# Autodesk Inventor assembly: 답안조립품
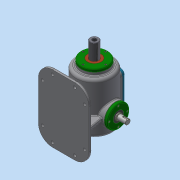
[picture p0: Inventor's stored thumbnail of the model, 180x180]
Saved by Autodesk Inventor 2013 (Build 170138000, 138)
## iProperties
Created: 2019-10
Part Number: 답안조립품
Document SubType Name: Assembly
Designer: dgall
Author: dgall
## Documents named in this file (17)
- C:\Users\dgall\Desktop\391004V1035\답안조립품.iam
- C:\Users\dgall\Desktop\391004V1035\본체.ipt
- C:\Users\dgall\Desktop\391004V1035\개스킷 B.ipt
- C:\Users\dgall\Desktop\391004V1035\베어링 6205.ipt
- 베어링 6205.ipt
- C:\Users\dgall\Desktop\391004V1035\볼트 M4x0.7.ipt
- C:\Users\dgall\Desktop\391004V1035\오일 실 25 38 8.ipt
- C:\Users\dgall\Desktop\391004V1035\축 커버.ipt
- C:\Users\dgall\Desktop\391004V1035\고정플레이트.ipt
- C:\Users\dgall\Desktop\391004V1035\상부커버.ipt
- C:\Users\dgall\Desktop\391004V1035\육각머리볼트 M4.ipt
- C:\Users\dgall\Desktop\391004V1035\가변스프링.ipt
- C:\Users\dgall\Desktop\391004V1035\개스킷 A.ipt
- C:\Users\dgall\Desktop\391004V1035\부시.ipt
- C:\Users\dgall\Desktop\391004V1035\슬라이드 커버.ipt
- C:\Users\dgall\Desktop\391004V1035\슬라이드.ipt
- C:\Users\dgall\Desktop\391004V1035\편심축.ipt
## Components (17 placed, 5 different names)
1. 개스킷 B:1
2. M4x0.7:1
3. M4x0.7:2
4. M4x0.7:3
5. M4x0.7:4
6. 개스킷 B:2
7. M4x0.7:5
8. M4x0.7:6
9. M4x0.7:7
10. M4x0.7:8
11. 고정플레이트:1 — 플러쉬:1
12. 가변스프링:1
13. 개스킷 A:1
14. M4x0.7:9
15. M4x0.7:10
16. M4x0.7:11
17. M4x0.7:12
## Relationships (1: Flush 1)
- 플러쉬:1 [Flush]: 고정플레이트:1
